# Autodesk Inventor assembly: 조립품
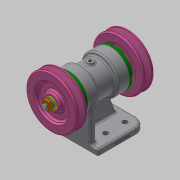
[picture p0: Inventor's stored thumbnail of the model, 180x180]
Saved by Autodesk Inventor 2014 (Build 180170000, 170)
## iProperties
Created: 2020-06
Part Number: 조립품
Document SubType Name: Assembly
Designer: kh
Author: kh
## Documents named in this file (12)
- C:\Users\kh\Desktop\700606V1025\조립품.iam
- C:\Users\kh\Desktop\700606V1025\본체.ipt
- C:\Users\kh\Desktop\700606V1025\베어링 6204.ipt
- C:\Users\kh\Desktop\700606V1025\축.ipt
- C:\Users\kh\Desktop\700606V1025\커버.ipt
- C:\Users\kh\Desktop\700606V1025\오일 실 20 32 5.ipt
- C:\Users\kh\Desktop\700606V1025\Ű 5x5x12.ipt
- C:\Users\kh\Desktop\700606V1025\V-벨트풀리.ipt
- C:\Users\kh\Desktop\700606V1025\평면 와셔 10x21.ipt
- C:\Users\kh\Desktop\700606V1025\스프링 와셔 10.ipt
- C:\Users\kh\Desktop\700606V1025\너트 M10.ipt
- C:\Users\kh\Desktop\700606V1025\볼트 M4.ipt
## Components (4 placed, 2 different names)
1. Ű 5x5x12:1 — Mate:17, Mate:18, Mate:19, Mate:24
2. Ű 5x5x12:2 — Mate:14, Mate:15, Mate:16, Mate:22
3. V-벨트풀리:1 — Mate:20, Mate:22, Mate:23, Mate:28
4. V-벨트풀리:2 — Mate:21, Mate:24, Mate:25, Mate:30
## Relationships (14: Mate 14)
- Mate:14: Ű 5x5x12:2
- Mate:15: Ű 5x5x12:2
- Mate:16: Ű 5x5x12:2
- Mate:17: Ű 5x5x12:1
- Mate:18: Ű 5x5x12:1
- Mate:19: Ű 5x5x12:1
- Mate:20: V-벨트풀리:1
- Mate:21: V-벨트풀리:2
- Mate:22: Ű 5x5x12:2 ↔ V-벨트풀리:1
- Mate:23: V-벨트풀리:1
- Mate:24: Ű 5x5x12:1 ↔ V-벨트풀리:2
- Mate:25: V-벨트풀리:2
- Mate:28: V-벨트풀리:1
- Mate:30: V-벨트풀리:2
